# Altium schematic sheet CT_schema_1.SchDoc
size 410 x 344 mm
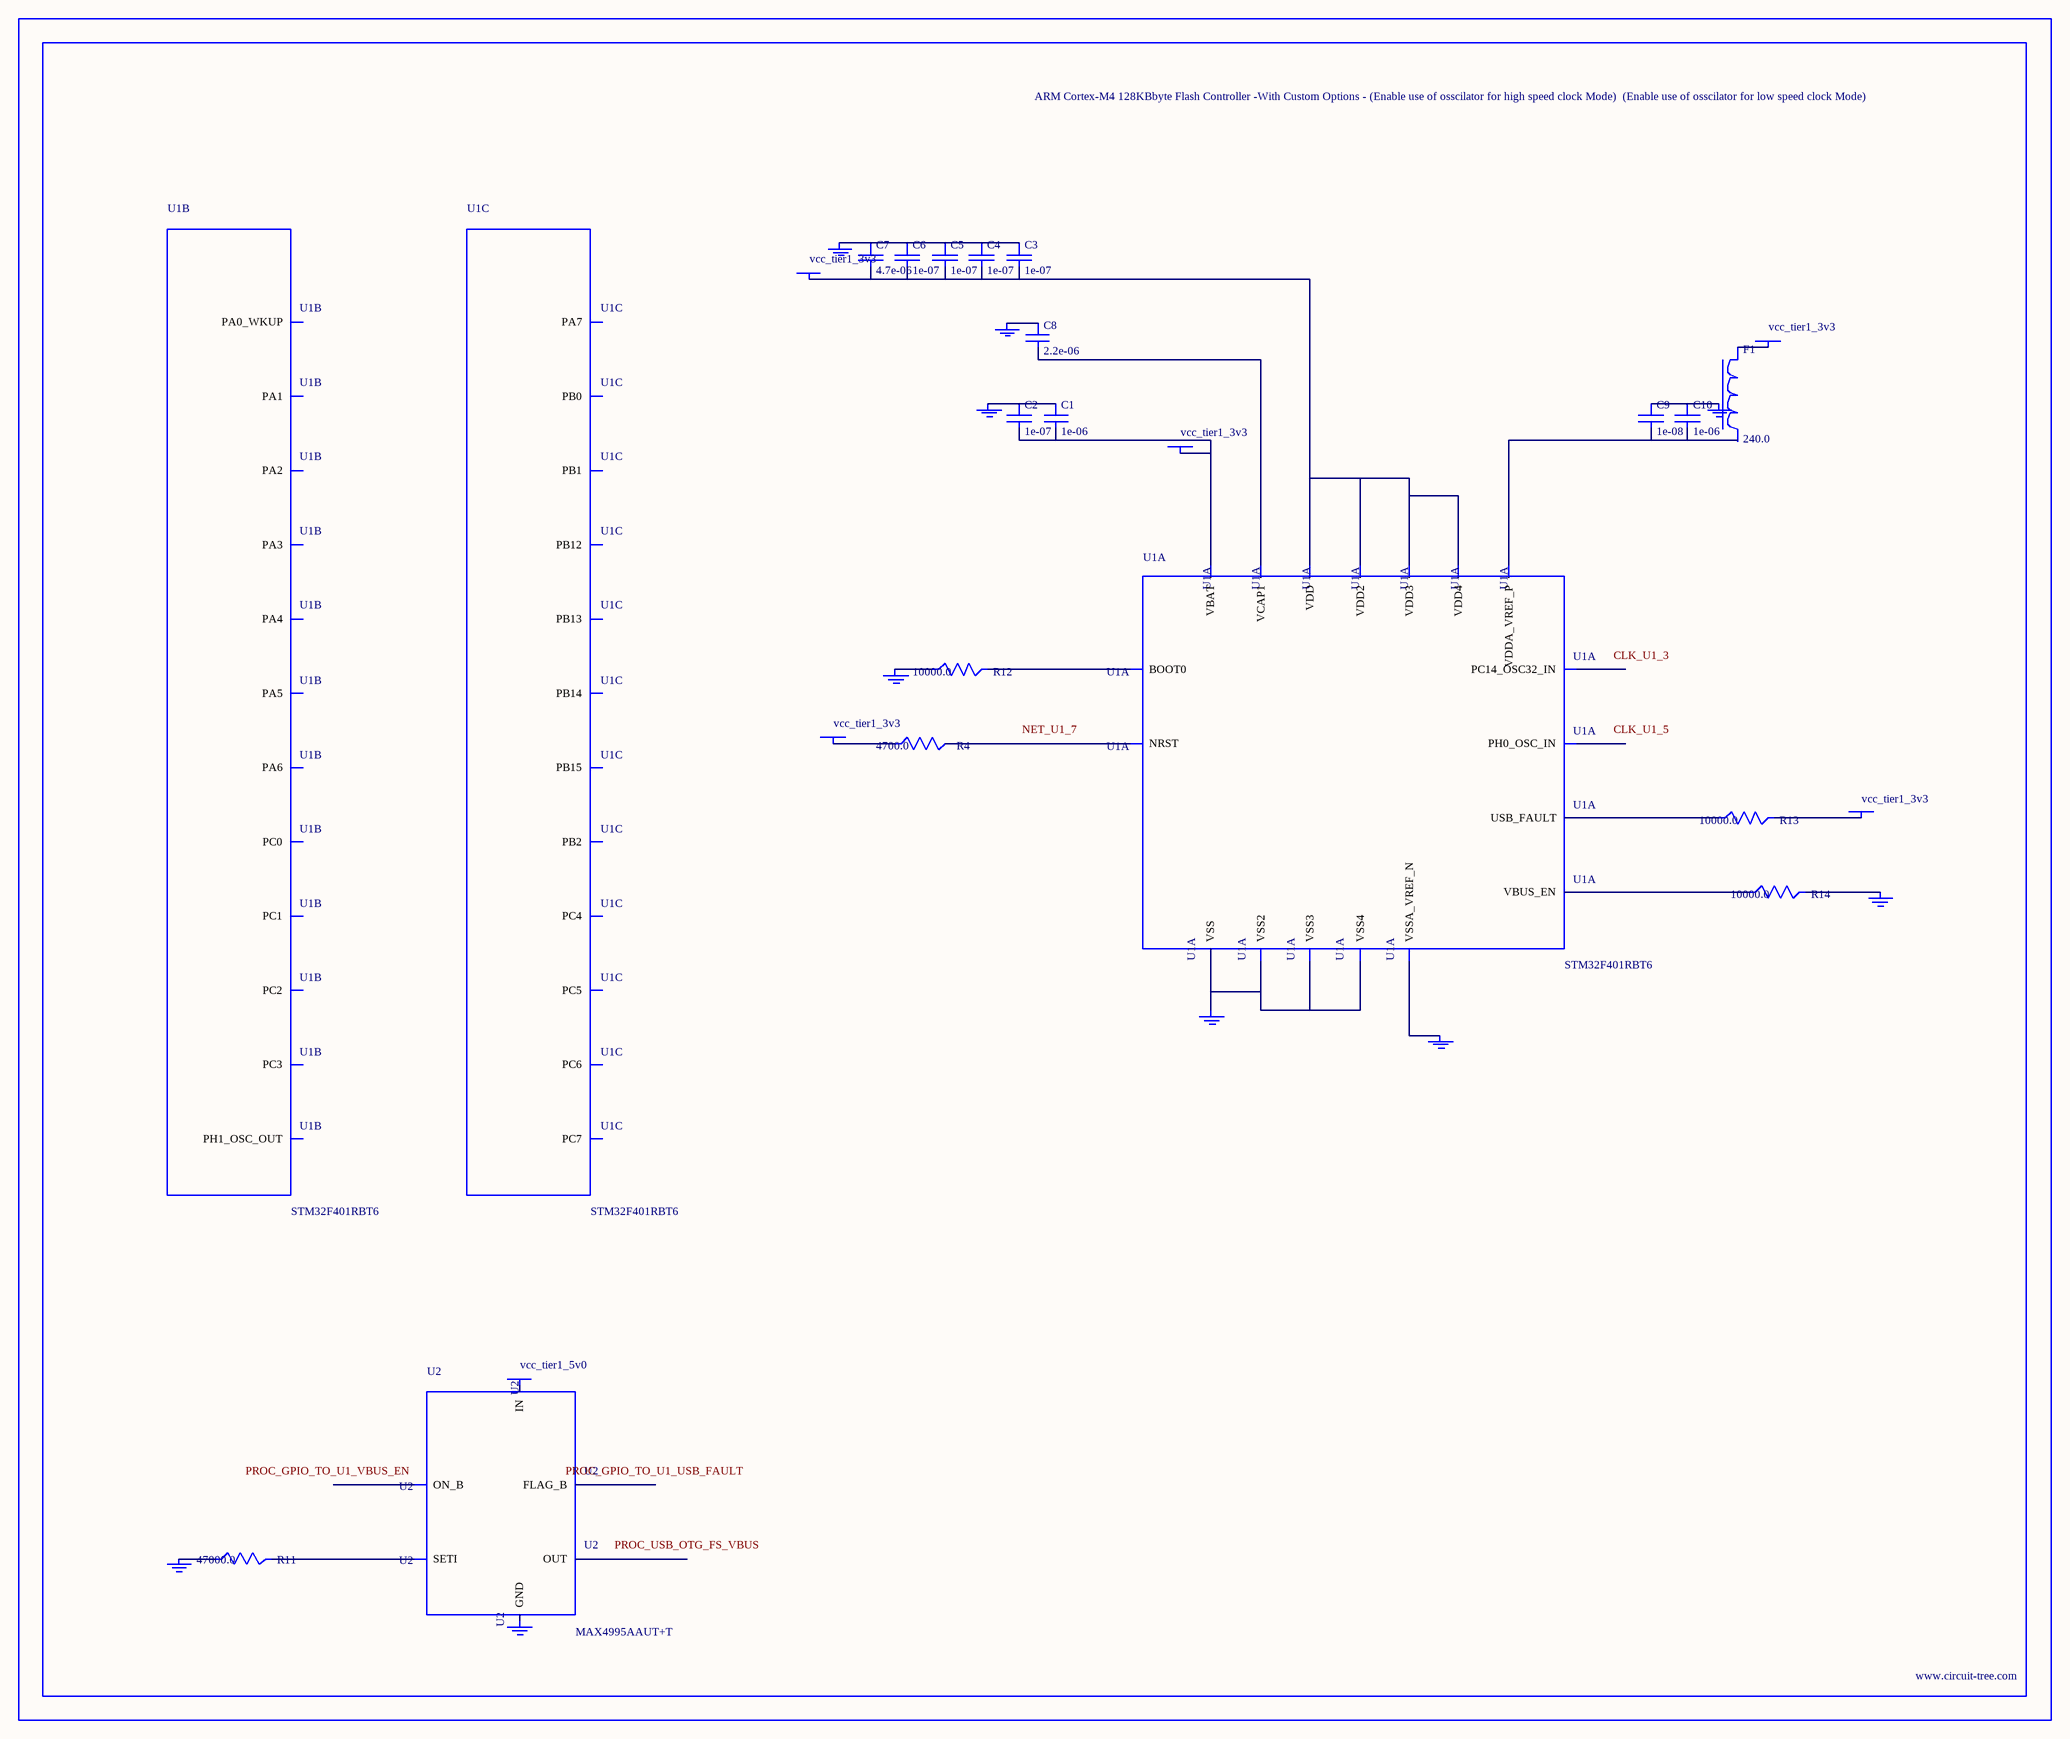
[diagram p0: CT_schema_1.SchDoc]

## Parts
BORDER0  (no value)
C1  1e-06  [C0603]
C2  1e-07  [C0603]
C3  1e-07  [C0603]
C4  1e-07  [C0603]
C5  1e-07  [C0603]
C6  1e-07  [C0603]
C7  4.7e-06  [C0603]
C8  2.2e-06  [C0603]
C9  1e-08  [C0603]
C10  1e-06  [C0603]
F1  240.0  [L0603]
GND_INSTANCE_0_0  (no value)
GND_INSTANCE_0_1  (no value)
GND_INSTANCE_0_2  (no value)
GND_INSTANCE_0_3  (no value)
GND_INSTANCE_0_4  (no value)
GND_INSTANCE_0_5  (no value)
GND_INSTANCE_0_6  (no value)
GND_INSTANCE_0_7  (no value)
GND_INSTANCE_0_8  (no value)
GND_INSTANCE_0_9  (no value)
POWER_INSTANCE_0_0  vcc_tier1_3v3
POWER_INSTANCE_0_1  vcc_tier1_3v3
POWER_INSTANCE_0_2  vcc_tier1_3v3
POWER_INSTANCE_0_3  vcc_tier1_3v3
POWER_INSTANCE_0_4  vcc_tier1_3v3
POWER_INSTANCE_0_5  vcc_tier1_5v0
R4  4700.0  [R0603]
R11  47000.0  [R0603]
R12  10000.0  [R0603]
R13  10000.0  [R0603]
R14  10000.0  [R0603]
U1  STM32F401RBT6  [LQFP64]  (parts A,B,C of 7)
U2  MAX4995AAUT+T  [SOT-23-6]

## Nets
NetC1_1: C1.1 C2.1 GND_INSTANCE_0_0.0(GND)
NetC1_2: C1.2 C2.2 POWER_INSTANCE_0_0.0(PWR) U1.1(VBAT)
NetC3_1: C3.1 C4.1 C5.1 C6.1 C7.1 GND_INSTANCE_0_4.0(GND)
NetC3_2: C3.2 C4.2 C5.2 C6.2 C7.2 POWER_INSTANCE_0_3.0(PWR) U1.19(VDD) U1.32(VDD2) U1.48(VDD3) U1.64(VDD4)
NetC8_1: C8.1 GND_INSTANCE_0_5.0(GND)
NetC8_2: C8.2 U1.30(VCAP1)
NetC9_1: C9.1 C10.1 GND_INSTANCE_0_3.0(GND)
NetC9_2: C9.2 C10.2 U1.13(VDDA_VREF_P)
NetF1_1: F1.1 POWER_INSTANCE_0_2.0(PWR)
NetGND_INSTANCE_0_1_0: GND_INSTANCE_0_1.0(GND) R14.2
NetGND_INSTANCE_0_2_0: GND_INSTANCE_0_2.0(GND) U1.12(VSSA_VREF_N)
NetGND_INSTANCE_0_6_0: GND_INSTANCE_0_6.0(GND) R12.1
NetGND_INSTANCE_0_7_0: GND_INSTANCE_0_7.0(GND) U1.18(VSS) U1.31(VSS2) U1.47(VSS3) U1.63(VSS4)
NetGND_INSTANCE_0_8_0: GND_INSTANCE_0_8.0(GND) R11.1
NetPOWER_INSTANCE_0_1_0: POWER_INSTANCE_0_1.0(PWR) R13.2
NetPOWER_INSTANCE_0_4_0: POWER_INSTANCE_0_4.0(PWR) R4.1
NetR4_2: R4.2 U1.7(NRST)
NetR11_2: R11.2 U2.3(SETI)
NetR12_2: R12.2 U1.60(BOOT0)
NetR13_1: R13.1 U1.4(USB_FAULT)
NetR14_1: R14.1 U1.2(VBUS_EN)

Not connected (* = marked no-connect by the designer): F1 2; GND_INSTANCE_0_9 0(GND); POWER_INSTANCE_0_5 0(PWR); U1 3(PC14_OSC32_IN) 5(PH0_OSC_IN) 6(PH1_OSC_OUT) 8(PC0) 9(PC1) 10(PC2) 11(PC3) 14(PA0_WKUP) 15(PA1) 16(PA2) 17(PA3) 20(PA4) 21(PA5) 22(PA6) 23(PA7) 24(PC4) 25(PC5) 26(PB0) 27(PB1) 28(PB2) 33(PB12) 34(PB13) 35(PB14) 36(PB15) 37(PC6) 38(PC7); U2 1(OUT) 2(GND) 4(ON_B) 5(IN) 6(FLAG_B)

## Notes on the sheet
- Labels drawn without touching a wire or pin: CLK_U1_3, CLK_U1_5, NET_U1_7, PROC_GPIO_TO_U1_USB_FAULT, PROC_GPIO_TO_U1_VBUS_EN, PROC_USB_OTG_FS_VBUS

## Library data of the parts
BORDER0 = BORDER_PAGE0
C1 C10 = C0603C105K3RACTU
C2-C6 = 06035C104K4Z2A
C7 = GRM188R6YA475KE15D
C8 = C0603C225K8RACTU
C9 = 06035C103K4Z2A
F1 = Z0603C241ASMST
GND_INSTANCE_0_0-GND_INSTANCE_0_9 = GND
POWER_INSTANCE_0_0-POWER_INSTANCE_0_5 = PWR
R4 = RC0603JR-074K7L
R11 = RC0603JR-0747KL
R12-R14 = RC0603JR-0710KL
